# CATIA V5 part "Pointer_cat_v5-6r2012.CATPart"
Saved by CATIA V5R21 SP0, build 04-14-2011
Part number: Follower
Bounding box of the stored display mesh (mm): x -9.942 to 9.942, y -9.942 to 9.942, z 0 to 100
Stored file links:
  D:\CATIA V5R21 E-RESOURCES\CATIA-V5R21\catia-v5r21-Tut\c16-catia-v5r21-tut\c16-catia-v5r21-tut03\Pointer_cat_v5r21.CATPart
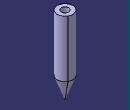
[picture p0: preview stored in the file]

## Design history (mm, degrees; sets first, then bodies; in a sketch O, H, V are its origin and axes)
Body1 (main body)
  Sketch1 on yz-plane, origin (0, 0, 0), H (0, 1, 0), V (0, 0, 1)
    line L1 (0, 0) -> (10, 27.4748)
    point P1 (10, 27.4748)
    line L2 (10, 27.4748) -> (10, 100)
    point P2 (10, 27.4748)
    point P3 (10, 100)
    point P4 (0, 100)
    point P5 (10, 91.3901)
    line L3 (0, 0) -> (0, 100)
    reference intersected line E1 through (0, 0) direction (-1, 0) from xy-plane
    reference intersected line E3 through (0, 0) direction (0, 1) from zx-plane
    line L4 (0, 100) -> (10, 100)
    point P6 (10, 100)
    angle L1 L3 = 20
    distance O P4 = 100
    length L4 = 10
    coincidence: P2 L1, P4 V, P5 L2, P2 P1, E3 P4, P1 L2, P6 L2, P6 P3
    vertical: L2 V, L3 V, E3 V
    horizontal: E1 H, L4 H
    perpendicularity: E1 L2
  Shaft1: profile Sketch1, axis Sketch1.L3, angle 360
  Sketch2 on face of Shaft1 from Sketch1.L4, origin (0, 0, 100), H (1, 0, 0), V (0, 1, 0)
    point P1 (0, 0)
  Hole1: placed by Sketch2, at (0, 0, 100) direction (0, 0, -1), diameter 10, depth 55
